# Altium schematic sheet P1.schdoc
size 297 x 209 mm; Symbol: Drawing-Symbol_A4; @Project Name: New Project_2026-05-12_14-23-33; @Page Count: 1; @Update Date: 2026-05-12; @Create Date: 2026-05-12; @Schematic Name: Schematic1; @Page No: 1; @Page Name: P1; Company: EasyEDA.com; Version: V1.0; Page Size: A4; @Create Time: 14:23:38; @Update Time: 14:51:03; Border: 1; Width: 1170; Height: 825; Region Start: 1; X Region Count: 6; Y Region Count: 4; Blade Width: 10; Title Block Position: 3; @Board Name: Board1; Device: Drawing-Symbol_A4
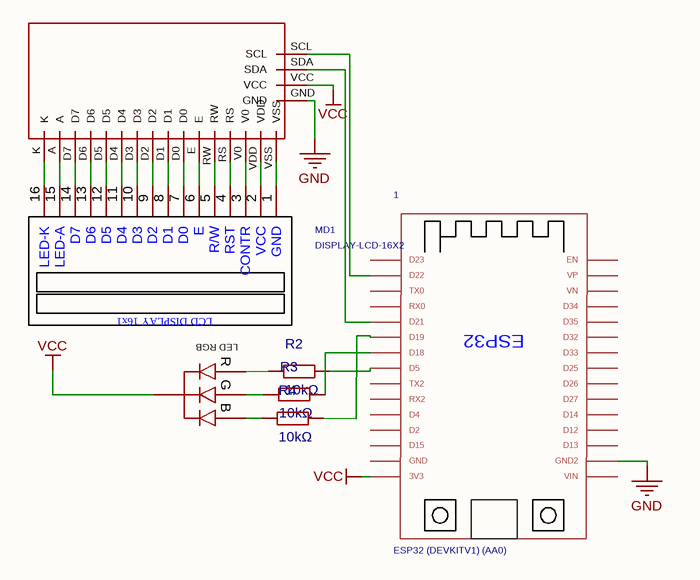
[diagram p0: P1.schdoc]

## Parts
1  ESP32 (DEVKITV1) (AA0)  [ESP32-DEVKITV1_ESP32-DEVKITV1]
LED1  led_rgb  [LED RGB 5MM (ARL5RGB)]  (value not drawn)
MD1  DISPLAY-LCD-16X2  [DISPLAY-LCD-16X2]
R2  10kΩ  [RES-TH_BD1.8-L3.2-P7.20-D0.4]
R3  10kΩ  [RES-TH_BD1.8-L3.2-P7.20-D0.4]
R4  10kΩ  [RES-TH_BD1.8-L3.2-P7.20-D0.4]
U1  lcd_i2c_pcf8574t  [I2C MODULE]  (value not drawn)

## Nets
GND: 1.GND2 U1.GND
VCC: 1.3V3 LED1.1 U1.VCC
Net1_D5: 1.D5 R2.2
Net1_D18: 1.D18 R3.2
Net1_D19: 1.D19 R4.2
Net1_D21: 1.D21 U1.SDA
Net1_D22: 1.D22 U1.SCL
NetLED1_B: LED1.B R4.1
NetLED1_G: LED1.G R3.1
NetLED1_R: LED1.R R2.1
NetMD1_1: MD1.1(GND) U1.VSS
NetMD1_2: MD1.2(VCC) U1.VDD
NetMD1_3: MD1.3(CONTR) U1.V0
NetMD1_4: MD1.4(RST) U1.RS
NetMD1_5: MD1.5(R/W) U1.RW
NetMD1_6: MD1.6(E) U1.E
NetMD1_7: MD1.7(D0) U1.D0
NetMD1_8: MD1.8(D1) U1.D1
NetMD1_9: MD1.9(D2) U1.D2
NetMD1_10: MD1.10(D3) U1.D3
NetMD1_11: MD1.11(D4) U1.D4
NetMD1_12: MD1.12(D5) U1.D5
NetMD1_13: MD1.13(D6) U1.D6
NetMD1_14: MD1.14(D7) U1.D7
NetMD1_15: MD1.15(LED-A) U1.A
NetMD1_16: MD1.16(LED-K) U1.K

Not connected (* = marked no-connect by the designer): 1 D2 D4 D12 D13 D14 D15 D23 D25 D26 D27 D32 D33 D34 D35 EN GND RX0 RX2 TX0 TX2 VIN VN VP

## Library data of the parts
LED1 = led_rgb: Add into BOM: yes
R2-R4 = Res_AXIAL-1/8W: Symbol: Res; ConvertToPcb: yes; ModelId: c828fea9a4a04d24ab219172637f10420819f05c4eef4c71ace90d822a990e87; ModelTransform: 299.212,70.746,0,0,0,0,0,0,-196.85
U1 = lcd_i2c_pcf8574t: Add into BOM: yes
